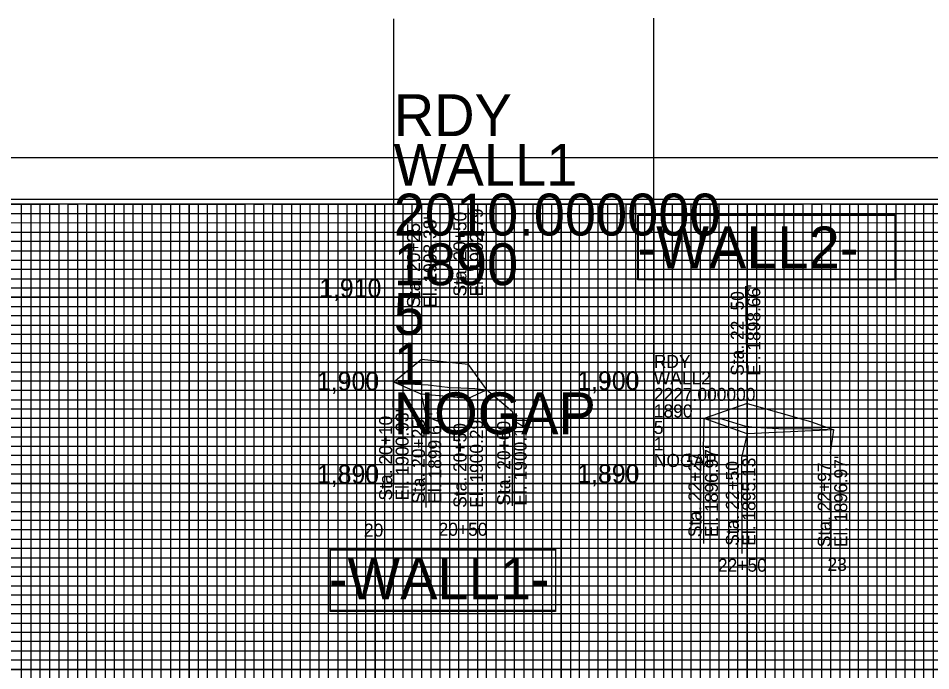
# Model space of a CAD drawing. Extents: x 557032 to 558716, y 513430 to 514605.
# Drawn here: x 557957.6 to 558448.2, y 514254.8 to 514605.4 of the extents above; entities that cross this region are included whole.
import ezdxf

# ---------------------------------------------------------------- set-up
doc = ezdxf.new("R2010")
doc.units = 0
for name, color, linetype in [('Exist Profile Cell', 7, 'Continuous'), ('Exist Vertical Profile Ground Line', 7, 'Continuous'), ('Exist Vertical Profile Horizontal Axis Label Major', 7, 'Continuous'), ('Exist Vertical Profile Vertical Axis Label', 7, 'Continuous'), ('Prop Vertical Profile Curve Label', 7, 'Continuous'), ('Prop VPI Label', 7, 'Continuous'), ('Scratch_Level_5', 7, 'Continuous'), ('Sheet Cutting Line CELL', 7, 'Continuous'), ('Sheet DOT Grid CELL', 7, 'Continuous'), ('Sheet Plot Border Inside CELL', 7, 'Continuous'), ('Sheet Plot Border Outside CELL', 7, 'Continuous'), ('Sheet Profile CELL', 7, 'Continuous'), ('Sheet Profile Grid Major CELL', 7, 'Continuous'), ('Sheet Profile Grid Middle CELL', 7, 'Continuous'), ('Sheet Profile Grid Minor CELL', 7, 'Continuous')]:
    doc.layers.add(name, color=color, linetype=linetype)

msp = doc.modelspace()

# ---------------------------------------------------------------- linework, layer by layer
at = {"layer": 'Exist Profile Cell'}
for p, q in [((558159.5, 514355.11), (558159.5, 514605.11)), ((558299.33, 514355.35), (558299.33, 514605.35)), ((558159.5, 514355.11), (558209.21, 514355.11)), ((558159.5, 514355.11), (558159.5, 514355.11)), ((558299.33, 514355.35), (558369.06, 514355.35)), ((558299.33, 514355.35), (558299.33, 514355.35))]:
    msp.add_line(p, q, dxfattribs=at)
at = {"layer": 'Exist Vertical Profile Ground Line'}
for p, q in [((558174.44, 514422.03), (558159.5, 514409.74)), ((558199.45, 514419.3), (558174.44, 514422.03)), ((558199.45, 514419.3), (558209.45, 514405.78)), ((558174.28, 514403.41), (558159.5, 514409.74)), ((558199.37, 514400.95), (558209.45, 514405.78)), ((558203.15, 514406.32), (558209.45, 514405.78)), ((558199.37, 514400.95), (558174.28, 514403.41)), ((558349.46, 514398.34), (558326.45, 514390.26)), ((558349.46, 514382.05), (558326.45, 514390.26)), ((558396.18, 514384.17), (558349.46, 514382.05))]:
    msp.add_line(p, q, dxfattribs=at)
for points in [[(558159.5, 514409.74), (558170.76, 514408.73), (558177.98, 514408.44), (558189.84, 514407), (558195.5, 514406.78)], [(558195.5, 514406.78), (558199.68, 514406.62), (558203.15, 514406.32)], [(558349.46, 514398.34), (558383.54, 514388.62), (558396.18, 514384.17)], [(558326.45, 514390.26), (558327.45, 514390.17), (558334.88, 514390.31), (558335.33, 514390.22), (558336.96, 514389.8), (558348.53, 514386.21), (558353.79, 514385.63), (558369.34, 514384.76), (558379.87, 514384.86), (558389.61, 514384.63), (558396.18, 514384.17)]]:
    msp.add_lwpolyline(points, dxfattribs=at)
at = {"layer": 'Prop Vertical Profile Curve Label'}
for points in [[(558291.09, 514499.66), (558428.9, 514499.66), (558428.9, 514465), (558291.09, 514465)], [(558125.57, 514319.66), (558246.43, 514319.66), (558246.43, 514287.13), (558125.57, 514287.13)]]:
    msp.add_lwpolyline(points, close=True, dxfattribs=at)
at = {"layer": 'Prop VPI Label'}
for p, q in [((558199.5, 514503.06), (558199.45, 514419.3)), ((558174.38, 514497.34), (558174.44, 514422.03)), ((558348.69, 514461.44), (558349.46, 514398.34)), ((558159.12, 514396.43), (558159.5, 514409.74)), ((558223.3, 514393.93), (558209.45, 514405.78)), ((558174.28, 514403.41), (558176.84, 514392.15)), ((558199.37, 514400.95), (558199.38, 514341.21)), ((558159.12, 514396.43), (558159.26, 514346.81)), ((558223.3, 514393.93), (558223.23, 514343.36)), ((558176.84, 514392.15), (558176.84, 514342.39)), ((558326.05, 514373.65), (558326.45, 514390.26)), ((558394.37, 514371.86), (558396.18, 514384.17)), ((558349.46, 514382.05), (558346.51, 514369.34)), ((558326.05, 514373.65), (558325.98, 514323.09)), ((558346.51, 514369.34), (558346.63, 514317.75)), ((558394.37, 514371.86), (558394.49, 514320.27))]:
    msp.add_line(p, q, dxfattribs=at)
for points in [[(558290.79, 514499.51), (558429.05, 514499.51), (558429.05, 514464.85), (558290.79, 514464.85)], [(558125.33, 514320.12), (558246.43, 514320.12), (558246.43, 514286.67), (558125.33, 514286.67)]]:
    msp.add_lwpolyline(points, close=True, dxfattribs=at)
at = {"layer": 'Scratch_Level_5'}
msp.add_lwpolyline([(557207.08, 514505.4), (557207.08, 513980.4), (558649.45, 513980.4), (558649.45, 514344.35), (558499.4, 514344.35), (558499.4, 514505.4)], close=True, dxfattribs=at)
at = {"layer": 'Sheet Cutting Line CELL'}
msp.add_line((558716.45, 514530.4), (557032.45, 514530.4), dxfattribs=at)
at = {"layer": 'Sheet DOT Grid CELL'}
for p, q in [((557999.45, 514005.4), (557999.45, 514505.4)), ((558049.45, 514005.4), (558049.45, 514505.4)), ((558099.45, 514005.4), (558099.45, 514505.4)), ((558149.45, 514005.4), (558149.45, 514505.4)), ((558199.45, 514005.4), (558199.45, 514505.4)), ((558249.45, 514005.4), (558249.45, 514505.4)), ((558299.45, 514005.4), (558299.45, 514505.4)), ((558349.45, 514005.4), (558349.45, 514505.4)), ((558399.45, 514005.4), (558399.45, 514505.4)), ((557999.45, 514010.97), (557999.45, 514488.82)), ((558049.45, 514010.93), (558049.45, 514488.82)), ((558099.45, 514010.9), (558099.45, 514488.82)), ((558149.45, 514010.86), (558149.45, 514488.82)), ((558249.45, 514010.79), (558249.45, 514488.82)), ((558299.45, 514010.75), (558299.45, 514488.82)), ((558349.45, 514010.71), (558349.45, 514488.82)), ((558399.45, 514010.68), (558399.45, 514488.82)), ((558499.4, 514455.4), (557199.45, 514455.4)), ((558484.51, 514455.4), (557203.74, 514455.4)), ((558499.4, 514405.4), (557199.45, 514405.4)), ((558484.51, 514405.4), (557203.83, 514405.4)), ((558499.45, 514355.4), (557199.45, 514355.4)), ((558484.51, 514355.4), (557203.92, 514355.4)), ((558699.45, 514305.4), (557199.45, 514305.4)), ((558693.5, 514305.4), (557204.01, 514305.4)), ((558699.45, 514255.4), (557199.45, 514255.4)), ((558693.5, 514255.4), (557204.1, 514255.4))]:
    msp.add_line(p, q, dxfattribs=at)
at = {"layer": 'Sheet Plot Border Inside CELL'}
msp.add_lwpolyline([(557045.45, 513452.85), (558711.95, 513452.85), (558711.95, 514507.95), (557045.45, 514507.95)], close=True, dxfattribs=at)
at = {"layer": 'Sheet Plot Border Outside CELL'}
msp.add_lwpolyline([(557032.45, 513430.4), (558716.45, 513430.4), (558716.45, 514530.4), (557032.45, 514530.4)], close=True, dxfattribs=at)
at = {"layer": 'Sheet Profile CELL'}
msp.add_lwpolyline([(558699.45, 514505.4), (557199.45, 514505.4), (557199.45, 513455.4), (558699.45, 513455.4)], close=True, dxfattribs=at)
at = {"layer": 'Sheet Profile Grid Major CELL'}
for points in [[(557949.45, 514005.4), (557999.45, 514005.4), (557999.45, 514505.4), (558049.45, 514505.4), (558049.45, 514005.4), (558099.45, 514005.4), (558099.45, 514505.4), (558149.45, 514505.4), (558149.45, 514005.4), (558199.45, 514005.4), (558199.45, 514505.4), (558249.45, 514505.4), (558249.45, 514005.4), (558299.45, 514005.4), (558299.45, 514505.4), (558349.45, 514505.4), (558349.45, 514005.4), (558399.45, 514005.4), (558399.45, 514505.4), (558449.45, 514505.4), (558449.45, 514005.4), (558499.45, 514005.4), (558499.45, 514505.4), (558525.75, 514505.4)], [(557999.45, 514010.97), (557999.45, 514488.82)], [(558049.45, 514488.82), (558049.45, 514010.93)], [(558099.45, 514010.9), (558099.45, 514488.82)], [(558149.45, 514488.82), (558149.45, 514010.86)], [(558199.45, 514010.82), (558199.45, 514488.82)], [(558249.45, 514488.82), (558249.45, 514010.79)], [(558299.45, 514010.75), (558299.45, 514488.82)], [(558349.45, 514488.82), (558349.45, 514010.71)], [(558399.45, 514010.68), (558399.45, 514488.82)], [(557199.45, 514455.4), (558499.45, 514455.4)], [(557203.74, 514455.4), (558484.51, 514455.4)], [(558499.45, 514405.4), (557199.45, 514405.4), (557199.45, 514355.4), (558499.45, 514355.4)], [(558484.51, 514405.4), (557203.83, 514405.4)], [(557203.92, 514355.4), (558484.51, 514355.4)], [(558699.45, 514305.4), (557199.45, 514305.4), (557199.45, 514255.4), (558699.45, 514255.4)], [(558693.5, 514305.4), (557204.01, 514305.4)], [(557204.1, 514255.4), (558693.5, 514255.4)]]:
    msp.add_lwpolyline(points, dxfattribs=at)
at = {"layer": 'Sheet Profile Grid Middle CELL'}
for p, q in [((557199.45, 514480.4), (558499.4, 514480.4)), ((557203.7, 514480.4), (558484.51, 514480.4))]:
    msp.add_line(p, q, dxfattribs=at)
for points in [[(557924.45, 514505.4), (557974.45, 514505.4), (557974.45, 514005.4), (558024.45, 514005.4), (558024.45, 514505.4), (558074.45, 514505.4), (558074.45, 514005.4), (558124.45, 514005.4), (558124.45, 514505.4), (558174.45, 514505.4), (558174.45, 514005.4), (558224.45, 514005.4), (558224.45, 514505.4), (558274.45, 514505.4), (558274.45, 514005.4), (558324.45, 514005.4), (558324.45, 514505.4), (558374.45, 514505.4), (558374.45, 514005.4), (558424.45, 514005.4), (558424.45, 514505.4), (558474.45, 514505.4)], [(557974.45, 514488.82), (557974.45, 514010.99)], [(558024.45, 514010.95), (558024.45, 514488.82)], [(558074.45, 514488.82), (558074.45, 514010.92)], [(558124.45, 514010.88), (558124.45, 514488.82)], [(558174.45, 514488.82), (558174.45, 514010.84)], [(558224.45, 514010.81), (558224.45, 514488.82)], [(558274.45, 514488.82), (558274.45, 514010.77)], [(558324.45, 514010.73), (558324.45, 514488.82)], [(558424.45, 514010.66), (558424.45, 514488.82)], [(558499.45, 514430.4), (557199.45, 514430.4), (557199.45, 514380.4), (558499.45, 514380.4)], [(558484.51, 514430.4), (557203.79, 514430.4)], [(557203.88, 514380.4), (558484.51, 514380.4)], [(558699.45, 514330.4), (557199.45, 514330.4), (557199.45, 514280.4), (558524.45, 514280.4)], [(558484.51, 514330.4), (557203.96, 514330.4)], [(557204.05, 514280.4), (558524.45, 514280.4)]]:
    msp.add_lwpolyline(points, dxfattribs=at)
at = {"layer": 'Sheet Profile Grid Minor CELL'}
for p, q in [((557249.45, 514500.4), (558499.45, 514500.4)), ((558499.45, 514495.4), (557249.45, 514495.05)), ((557249.45, 514490.4), (558499.45, 514490.4)), ((558499.4, 514370.4), (557249.45, 514370.4)), ((558484.51, 514370.4), (557249.45, 514370.4)), ((558499.45, 514365.4), (557249.45, 514365.4)), ((558484.51, 514365.4), (557249.45, 514365.4)), ((558499.45, 514360.4), (557249.45, 514360.4)), ((558484.51, 514360.4), (557249.45, 514360.4)), ((557249.45, 514350.4), (558499.45, 514350.4)), ((557249.45, 514350.4), (558484.51, 514350.4)), ((558499.45, 514345.4), (557249.45, 514345.4)), ((558484.51, 514345.4), (557249.45, 514345.4)), ((557249.45, 514340.4), (558649.45, 514340.4)), ((557249.45, 514340.4), (558484.51, 514340.4)), ((558649.45, 514320.4), (557249.45, 514320.4)), ((558484.51, 514320.4), (557249.45, 514320.4)), ((557249.45, 514315.4), (558649.45, 514315.4)), ((557249.45, 514315.4), (558649.45, 514315.4)), ((558649.45, 514295.4), (557249.45, 514295.4)), ((558649.45, 514295.4), (557249.45, 514295.4)), ((557249.45, 514290.4), (558649.45, 514290.4)), ((557249.45, 514290.4), (558649.45, 514290.4)), ((558649.45, 514270.4), (557249.45, 514270.4)), ((558649.45, 514270.4), (557249.45, 514270.4)), ((557249.45, 514265.4), (558649.45, 514265.4)), ((557249.45, 514265.4), (558649.45, 514265.4)), ((558649.45, 514260.4), (557249.45, 514260.4)), ((558649.45, 514260.4), (557249.45, 514260.4))]:
    msp.add_line(p, q, dxfattribs=at)
for points in [[(557959.45, 514005.4), (557959.45, 514505.4), (557964.45, 514505.4), (557964.45, 514005.4)], [(557969.45, 514005.4), (557969.45, 514505.4), (557979.45, 514505.4), (557979.45, 514005.4)], [(557984.45, 514005.4), (557984.45, 514505.4), (557989.45, 514505.4), (557989.45, 514005.4)], [(557994.45, 514005.4), (557994.45, 514505.4), (558004.45, 514505.4), (558004.45, 514005.4)], [(558009.45, 514005.4), (558009.45, 514505.4), (558014.45, 514505.4), (558014.45, 514005.4)], [(558019.45, 514005.4), (558019.45, 514505.4), (558029.45, 514505.4), (558029.45, 514005.4)], [(558034.45, 514005.4), (558034.45, 514505.4), (558039.45, 514505.4), (558039.45, 514005.4)], [(558044.45, 514005.4), (558044.45, 514505.4), (558054.45, 514505.4), (558054.45, 514005.4)], [(558059.45, 514005.4), (558059.45, 514505.4), (558064.45, 514505.4), (558064.45, 514005.4)], [(558069.45, 514005.4), (558069.45, 514505.4), (558079.45, 514505.4), (558079.45, 514005.4)], [(558084.45, 514005.4), (558084.45, 514505.4), (558089.45, 514505.4), (558089.45, 514005.4)], [(558094.45, 514005.4), (558094.45, 514505.4), (558104.45, 514505.4), (558104.45, 514005.4)], [(558109.45, 514005.4), (558109.45, 514505.4), (558114.45, 514505.4), (558114.45, 514005.4)], [(558119.45, 514005.4), (558119.45, 514505.4), (558129.45, 514505.4), (558129.45, 514005.4)], [(558134.45, 514005.4), (558134.45, 514505.4), (558139.45, 514505.4), (558139.45, 514005.4)], [(558144.45, 514005.4), (558144.45, 514505.4), (558154.45, 514505.4), (558154.45, 514005.4)], [(558159.45, 514005.4), (558159.45, 514505.4), (558164.45, 514505.4), (558164.45, 514005.4)], [(558169.45, 514005.4), (558169.45, 514505.4), (558179.45, 514505.4), (558179.45, 514005.4)], [(558184.45, 514005.4), (558184.45, 514505.4), (558189.45, 514505.4), (558189.45, 514005.4)], [(558194.45, 514005.4), (558194.45, 514505.4), (558204.45, 514505.4), (558204.45, 514005.4)], [(558209.45, 514005.4), (558209.45, 514505.4), (558214.45, 514505.4), (558214.45, 514005.4)], [(558219.45, 514005.4), (558219.45, 514505.4), (558229.45, 514505.4), (558229.45, 514005.4)], [(558234.45, 514005.4), (558234.45, 514505.4), (558239.45, 514505.4), (558239.45, 514005.4)], [(558244.45, 514005.4), (558244.45, 514505.4), (558254.45, 514505.4), (558254.45, 514005.4)], [(558259.45, 514005.4), (558259.45, 514505.4), (558264.45, 514505.4), (558264.45, 514005.4)], [(558269.45, 514005.4), (558269.45, 514505.4), (558279.45, 514505.4), (558279.45, 514005.4)], [(558284.45, 514005.4), (558284.45, 514505.4), (558289.45, 514505.4), (558289.45, 514005.4)], [(558294.45, 514005.4), (558294.45, 514505.4), (558304.45, 514505.4), (558304.45, 514005.4)], [(558309.45, 514005.4), (558309.45, 514505.4), (558314.45, 514505.4), (558314.45, 514005.4)], [(558319.45, 514005.4), (558319.45, 514505.4), (558329.45, 514505.4), (558329.45, 514005.4)], [(558334.45, 514005.4), (558334.45, 514505.4), (558339.45, 514505.4), (558339.45, 514005.4)], [(558344.45, 514005.4), (558344.45, 514505.4), (558354.45, 514505.4), (558354.45, 514005.4)], [(558359.45, 514005.4), (558359.45, 514505.4), (558364.45, 514505.4), (558364.45, 514005.4)], [(558369.45, 514005.4), (558369.45, 514505.4), (558379.45, 514505.4), (558379.45, 514005.4)], [(558384.45, 514005.4), (558384.45, 514505.4), (558389.45, 514505.4), (558389.45, 514005.4)], [(558389.45, 514005.4), (558394.45, 514005.4), (558394.45, 514505.4), (558404.45, 514505.4), (558404.45, 514005.4), (558409.45, 514005.4), (558409.45, 514505.4), (558414.45, 514505.4), (558414.45, 514005.4), (558419.45, 514005.4), (558419.45, 514505.4), (558429.45, 514505.4), (558429.45, 514005.4), (558434.45, 514005.4), (558434.45, 514505.4), (558439.45, 514505.4), (558439.45, 514005.4), (558444.45, 514005.4), (558444.45, 514505.4), (558454.45, 514505.4)], [(557959.45, 514011), (557959.45, 514488.82)], [(557964.45, 514488.82), (557964.45, 514011)], [(557969.45, 514010.99), (557969.45, 514488.82)], [(557979.45, 514488.82), (557979.45, 514010.99)], [(557984.45, 514010.98), (557984.45, 514488.82)], [(557989.45, 514488.82), (557989.45, 514010.98)], [(557994.45, 514010.97), (557994.45, 514488.82)], [(558004.45, 514488.82), (558004.45, 514010.97)], [(558009.45, 514010.96), (558009.45, 514488.82)], [(558014.45, 514488.82), (558014.45, 514010.96)], [(558019.45, 514010.96), (558019.45, 514488.82)], [(558029.45, 514488.82), (558029.45, 514010.95)], [(558034.45, 514010.95), (558034.45, 514488.82)], [(558039.45, 514488.82), (558039.45, 514010.94)], [(558044.45, 514010.94), (558044.45, 514488.82)], [(558054.45, 514488.82), (558054.45, 514010.93)], [(558059.45, 514010.93), (558059.45, 514488.82)], [(558064.45, 514488.82), (558064.45, 514010.92)], [(558069.45, 514010.92), (558069.45, 514488.82)], [(558079.45, 514488.82), (558079.45, 514010.91)], [(558084.45, 514010.91), (558084.45, 514488.82)], [(558089.45, 514488.82), (558089.45, 514010.91)], [(558094.45, 514010.9), (558094.45, 514488.82)], [(558104.45, 514488.82), (558104.45, 514010.89)], [(558109.45, 514010.89), (558109.45, 514488.82)], [(558114.45, 514488.82), (558114.45, 514010.89)], [(558119.45, 514010.88), (558119.45, 514488.82)], [(558129.45, 514488.82), (558129.45, 514010.88)], [(558134.45, 514010.87), (558134.45, 514488.82)], [(558139.45, 514488.82), (558139.45, 514010.87)], [(558144.45, 514010.86), (558144.45, 514488.82)], [(558154.45, 514488.82), (558154.45, 514010.86)], [(558159.45, 514010.85), (558159.45, 514488.82)], [(558164.45, 514488.82), (558164.45, 514010.85)], [(558169.45, 514010.85), (558169.45, 514488.82)], [(558179.45, 514488.82), (558179.45, 514010.84)], [(558184.45, 514010.84), (558184.45, 514488.82)], [(558189.45, 514488.82), (558189.45, 514010.83)], [(558194.45, 514010.83), (558194.45, 514488.82)], [(558204.45, 514488.82), (558204.45, 514010.82)], [(558209.45, 514010.82), (558209.45, 514488.82)], [(558214.45, 514488.82), (558214.45, 514010.81)], [(558219.45, 514010.81), (558219.45, 514488.82)], [(558229.45, 514488.82), (558229.45, 514010.8)], [(558234.45, 514010.8), (558234.45, 514488.82)], [(558239.45, 514488.82), (558239.45, 514010.8)], [(558244.45, 514010.79), (558244.45, 514488.82)], [(558254.45, 514488.82), (558254.45, 514010.78)], [(558259.45, 514010.78), (558259.45, 514488.82)], [(558264.45, 514488.82), (558264.45, 514010.78)], [(558269.45, 514010.77), (558269.45, 514488.82)], [(558279.45, 514488.82), (558279.45, 514010.77)], [(558284.45, 514010.76), (558284.45, 514488.82)], [(558289.45, 514488.82), (558289.45, 514010.76)], [(558294.45, 514010.76), (558294.45, 514488.82)], [(558304.45, 514488.82), (558304.45, 514010.75)], [(558309.45, 514010.74), (558309.45, 514488.82)], [(558314.45, 514488.82), (558314.45, 514010.74)], [(558319.45, 514010.74), (558319.45, 514488.82)], [(558329.45, 514488.82), (558329.45, 514010.73)], [(558334.45, 514010.73), (558334.45, 514488.82)], [(558339.45, 514488.82), (558339.45, 514010.72)], [(558344.45, 514010.72), (558344.45, 514488.82)], [(558354.45, 514488.82), (558354.45, 514010.71)], [(558359.45, 514010.71), (558359.45, 514488.82)], [(558364.45, 514488.82), (558364.45, 514010.7)], [(558369.45, 514010.7), (558369.45, 514488.82)], [(558379.45, 514488.82), (558379.45, 514010.69)], [(558384.45, 514010.69), (558384.45, 514488.82)], [(558389.45, 514488.82), (558389.45, 514010.69)], [(558394.45, 514010.68), (558394.45, 514488.82)], [(558404.45, 514488.82), (558404.45, 514010.67)], [(558409.45, 514010.67), (558409.45, 514488.82)], [(558414.45, 514488.82), (558414.45, 514010.67)], [(558419.45, 514010.66), (558419.45, 514488.82)], [(558429.45, 514488.82), (558429.45, 514010.66)], [(558434.45, 514015.03), (558434.45, 514488.82)], [(558439.45, 514488.82), (558439.45, 514023.01)], [(558444.45, 514030.99), (558444.45, 514488.82)], [(558499.45, 514485.4), (557249.45, 514485.4), (557249.45, 514475.4), (558499.45, 514475.4)], [(558484.51, 514485.4), (557249.45, 514485.4), (557249.45, 514475.4), (558484.51, 514475.4)], [(558499.4, 514470.4), (557249.45, 514470.4), (557249.45, 514465.4), (558499.45, 514465.4)], [(558484.51, 514470.4), (557249.45, 514470.4), (557249.45, 514465.4), (558484.51, 514465.4)], [(558499.45, 514460.4), (557249.45, 514460.4), (557249.45, 514450.4), (558499.45, 514450.4)], [(558484.51, 514460.4), (557249.45, 514460.4), (557249.45, 514450.4), (558484.51, 514450.4)], [(558499.45, 514445.4), (557249.45, 514445.4), (557249.45, 514440.4), (558499.45, 514440.4)], [(558484.51, 514445.4), (557249.45, 514445.4), (557249.45, 514440.4), (558484.51, 514440.4)], [(558499.45, 514435.4), (557249.45, 514435.4), (557249.45, 514425.4), (558499.45, 514425.4)], [(558484.51, 514435.4), (557249.45, 514435.4), (557249.45, 514425.4), (558484.51, 514425.4)], [(558499.45, 514420.4), (557249.45, 514420.4), (557249.45, 514415.4), (558499.45, 514415.4)], [(558484.51, 514420.4), (557249.45, 514420.4), (557249.45, 514415.4), (558484.51, 514415.4)], [(558499.45, 514410.4), (557249.45, 514410.4), (557249.45, 514400.4), (558499.45, 514400.4)], [(558484.51, 514410.4), (557249.45, 514410.4), (557249.45, 514400.4), (558484.51, 514400.4)], [(558499.45, 514395.3), (557249.55, 514395.3), (557249.55, 514390.4), (558499.45, 514390.4)], [(558484.51, 514395.3), (557249.55, 514395.3), (557249.55, 514390.4), (558484.51, 514390.4)], [(558499.45, 514385.4), (557249.45, 514385.4), (557249.45, 514375.4), (558499.45, 514375.4)], [(558484.51, 514385.4), (557249.45, 514385.4), (557249.45, 514375.4), (558484.51, 514375.4)], [(558649.45, 514335.4), (557249.45, 514335.4), (557249.45, 514325.4), (558649.45, 514325.4)], [(558484.51, 514335.4), (557249.45, 514335.4), (557249.45, 514325.4), (558484.51, 514325.4)], [(558649.45, 514310.4), (557249.45, 514310.4), (557249.45, 514300.4), (558649.45, 514300.4)], [(558649.45, 514310.4), (557249.45, 514310.4), (557249.45, 514300.4), (558649.45, 514300.4)], [(558649.45, 514285.4), (557249.45, 514285.4), (557249.45, 514275.4), (558649.45, 514275.4)], [(558649.45, 514285.4), (557249.45, 514285.4), (557249.45, 514275.4), (558649.45, 514275.4)]]:
    msp.add_lwpolyline(points, dxfattribs=at)

# ---------------------------------------------------------------- texts
at = {"layer": 'Exist Profile Cell'}
for s, height, p in [('RDY', 22.5, (558159.5, 514542.01)), ('WALL1', 22.5, (558159.5, 514515.31)), ('2010.000000', 22.5, (558159.5, 514488.61)), ('1890', 22.5, (558159.5, 514461.91)), ('5', 22.5, (558159.5, 514435.21)), ('1', 22.5, (558159.5, 514408.51)), ('RDY', 7, (558299.33, 514417.47)), ('WALL2', 7, (558299.33, 514408.6)), ('NOGAP', 22.5, (558159.5, 514381.81)), ('2227.000000', 7, (558299.33, 514399.72)), ('1890', 7, (558299.33, 514390.85)), ('5', 7, (558299.33, 514381.97)), ('1', 7, (558299.33, 514373.1)), ('NOGAP', 7, (558299.33, 514364.23))]:
    msp.add_text(s, height=height, dxfattribs=at).set_placement(p)
at = {"layer": 'Exist Vertical Profile Horizontal Axis Label Major'}
for s, p in [('20', (558143.48, 514326.81)), ('20+50', (558183.6, 514327.27)), ('23', (558392.71, 514308.42)), ('22+50', (558333.79, 514307.96))]:
    msp.add_text(s, height=7, dxfattribs=at).set_placement(p)
at = {"layer": 'Exist Vertical Profile Vertical Axis Label'}
for s, p in [('1,910', (558119.4, 514455.36)), ('1,900', (558118.2, 514405.36)), ('1,900', (558258.15, 514405.65)), ('1,890', (558118.2, 514355.36)), ('1,890', (558258.15, 514355.65))]:
    msp.add_text(s, height=10, dxfattribs=at).set_placement(p)
at = {"layer": 'Prop Vertical Profile Curve Label'}
for s, p in [('-WALL2-', (558290.58, 514470.96)), ('-WALL1-', (558124.56, 514293.15))]:
    msp.add_text(s, height=22.5, dxfattribs=at).set_placement(p)
at = {"layer": 'Prop VPI Label'}
for s, p in [("El. 1902.79'", (558207.44, 514455.84)), ("El. 1903.38'", (558182.51, 514449.8)), ('Sta. 20+50', (558198.56, 514455.84)), ('Sta. 20+25', (558173.64, 514449.8)), ('Sta. 22+50', (558347.72, 514413.2)), ("El. 1898.66'", (558356.6, 514413.2)), ("El. 1900.93'", (558167.52, 514346.21)), ('Sta. 20+10', (558158.64, 514346.21)), ('Sta. 20+25', (558176.22, 514344.5)), ("El. 1899.67'", (558185.09, 514344.5)), ("El. 1900.29'", (558207.47, 514342.28)), ("El. 1900.14'", (558230.99, 514343.48)), ('Sta. 20+50', (558198.6, 514342.28)), ('Sta. 20+60', (558222.12, 514343.48)), ("El. 1896.97'", (558333.82, 514326.5)), ('Sta. 22+27', (558324.94, 514326.5)), ("El. 1895.13'", (558353.94, 514321.89)), ("El. 1896.97'", (558403.3, 514321.13)), ('Sta. 22+50', (558345.07, 514321.89)), ('Sta. 22+97', (558394.43, 514321.13))]:
    msp.add_text(s, height=7, rotation=90, dxfattribs=at).set_placement(p)

doc.saveas('drawing.dxf')
